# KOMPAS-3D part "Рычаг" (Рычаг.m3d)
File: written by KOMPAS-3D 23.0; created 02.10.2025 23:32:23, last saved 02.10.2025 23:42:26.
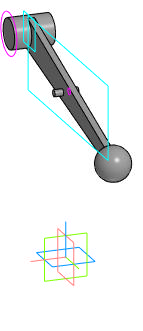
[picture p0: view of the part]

Document properties: Автор: Inspektor_Kot; Полное имя файла: I:\Autodesk Inventor Projects\ИМ-ИТ ЦД\Вариант 10\Рычаг.m3d

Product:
- Part/product: Рычаг
    Масса: 1.054844

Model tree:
1. Эскиз:1  (with: Элемент выдавливания:3, Элемент выдавливания:8)
2. Элемент выдавливания:1
     Расстояние 2 = 48
3. Средняя плоскость:1  (with: Элемент выдавливания:1)
4. Эскиз:2  (with: Элемент выдавливания:1)
5. Элемент выдавливания:2
     Расстояние 1 = 8
6. Эскиз:3  (with: Элемент выдавливания:2)
7. Эскиз:4  (with: Элемент выдавливания:2)
8. Элемент выдавливания:4
     Расстояние 1 = 10; Расстояние 2 = 18
9. Средняя плоскость:2  (with: Элемент выдавливания:2)
10. Эскиз:5  (with: Элемент выдавливания:2)
11. Элемент вращения:1
     Угол 1 = 360
12. Эскиз:6  (with: Элемент выдавливания:1)

Referenced files in I:\Autodesk Inventor Projects\ИМ-ИТ ЦД\Вариант 10\: Прибор контроля заготовок..a3d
